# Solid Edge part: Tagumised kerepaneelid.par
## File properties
Author: Türk
Template: iso part.par
Last saved by: Türk
Revision: 43
Application: Solid Edge
Accuracy: 0,990
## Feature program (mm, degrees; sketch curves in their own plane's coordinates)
base feature "unnamed BaseFeature 1"
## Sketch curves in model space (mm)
line (-628.6052, 2432.4035, 550) -> (-645.1556, 2300, 550)
line (-650, 2300, 550) -> (-645.1556, 2300, 550)
line (-636.8804, 2366.2017, 550) -> (-628.6052, 2432.4035, 550)
arc centre (-529.3774, 2420, 550) radius 100 from (-529.3774, 2520, 550) through (-597.6984, 2493.0222, 550) to (-628.6052, 2432.4035, 550)
line (-645.1556, 2300, 550) -> (-650.1946, 2300, 550)
line (-633.5666, 2433.0236, 550) -> (-650.1946, 2300, 550)
arc centre (-529.3774, 2420, 550) radius 105 from (-529.3774, 2525, 550) through (-601.1145, 2496.6733, 550) to (-633.5666, 2433.0236, 550)
line (0, 2525, 550) -> (-529.3774, 2525, 550)
line (0, 2520, 550) -> (0, 2525, 550)
line (0, 2520, 550) -> (-529.3774, 2520, 550)
spline (-818.1579, 3065, 375.0419) -> (-818.1579, 2713.384, 451.0389) -> (-818.1579, 2300, 485.7901)
spline (-814.1854, 3065, 370.7888) -> (-814.2314, 3065, 370.782) -> (-814.2774, 3065, 370.7752)
spline (-650, 3065, 400) -> (-367.1751, 3065, 434.5988) -> (0, 3065, 450)
spline (-650, 3065, 400) -> (-323.796, 3065, 437.7144) -> (0, 3065, 450)
spline (-813.3651, 3065, 373.7347) -> (-813.373, 3065, 373.7089) -> (-813.381, 3065, 373.6831)
line (-813.381, 3065, 373.6831) -> (-813.365, 3065, 373.6785)
spline (-650, 3065, -150) -> (-851.9751, 3065, 62.3442) -> (-818.1579, 3065, 375.0419)
spline (-818.1579, 3065, 375.0419) -> (-851.9751, 3065, 62.3442) -> (-650, 3065, -150)
line (-649.7381, 3065, 400.0481) -> (-650, 3065, 400)
spline (0, 3065, 450) -> (-366.9982, 3065, 434.6124) -> (-649.7381, 3065, 400.0481)
spline (0, 3065, 450) -> (-337.9024, 3065, 436.7487) -> (-650, 3065, 400)
spline (-258.0604, 2300, 544.9468) -> (-258.0298, 2300, 544.9472) -> (-257.9993, 2300, 544.9476)
line (-814.5901, 2300, 481.8003) -> (-814.5882, 2300, 481.8035)
spline (-650.0163, 2300, -144.8502) -> (-650.0081, 2300, -144.8522) -> (-650, 2300, -144.8541)
line (-650, 2300, 550) -> (-818.1579, 2300, 485.7901)
line (-650, 2300, 550) -> (-645.1556, 2300, 550.0371)
line (135.3081, 2300, 550) -> (541.297, 2300, 550)
spline (541.297, 2300, 550) -> (338.3005, 2300, 550) -> (135.3081, 2300, 550)
line (0, 2300, 550) -> (1.057, 2300, 550)
spline (-0.2583, 2300, 549.9923) -> (-0.1292, 2300, 549.9961) -> (0, 2300, 550)
spline (2.114, 2300, 550) -> (0.9278, 2300, 550) -> (-0.2583, 2300, 549.9923)
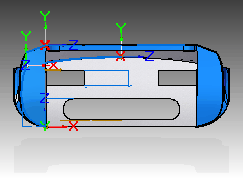
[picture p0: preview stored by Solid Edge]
